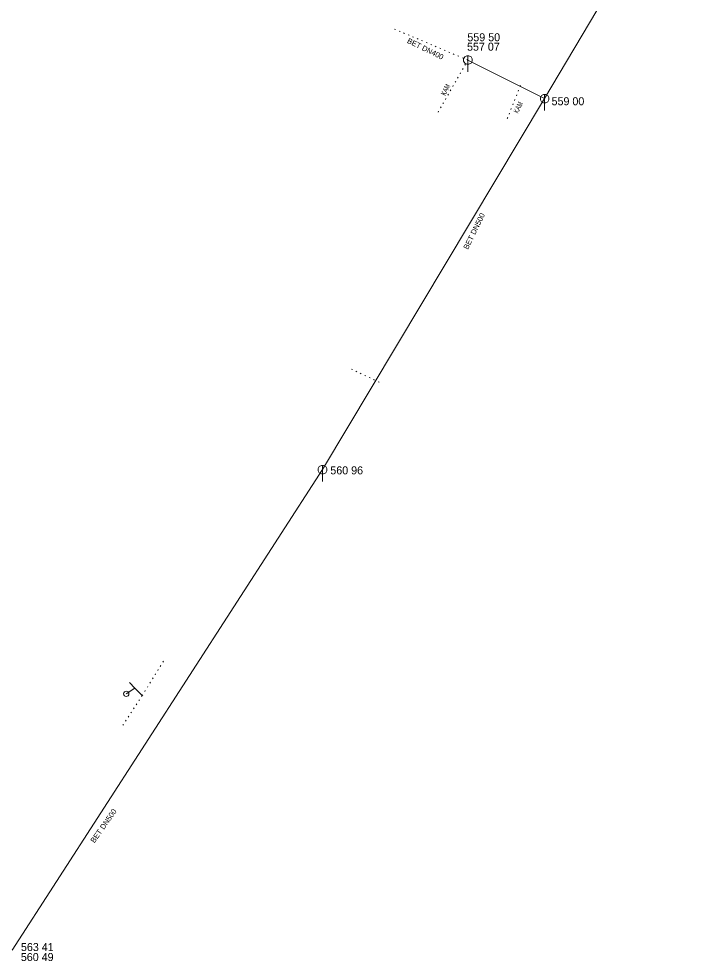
# Model space of a CAD drawing. Extents: x -710806 to -710046, y -1116920 to -1116046.
# Drawn here: x -710518.2 to -710454.5, y -1116662.7 to -1116574.5 of the extents above; entities that cross this region are included whole.
import ezdxf
from ezdxf.enums import TextEntityAlignment as Align

# ---------------------------------------------------------------- set-up
doc = ezdxf.new("R2010")
doc.units = 0
doc.header["$LTSCALE"] = 0.3
doc.linetypes.add('DOTTED', pattern=[1.5, 0.3, -1.2])
for name, color, linetype, lineweight in [('40', 7, 'Continuous', 13), ('41', 7, 'Continuous', 13), ('45', 7, 'DOTTED', 13)]:
    doc.layers.add(name, color=color, linetype=linetype, lineweight=lineweight)
doc.layers.add('43', color=7, linetype='Continuous')
doc.layers.add('44', color=7, linetype='Continuous')

msp = doc.modelspace()

# ---------------------------------------------------------------- linework, layer by layer
at = {"layer": '40'}
msp.add_line((-710468.921, -1116581.933), (-710454.536, -1116557.596), dxfattribs=at)
at = {"layer": '40', "linetype": 'DOTTED'}
for p, q in [((-710476.116, -1116578.317), (-710483.097, -1116575.374)), ((-710506.638, -1116637.858), (-710504.607, -1116634.576)), ((-710506.638, -1116637.858), (-710508.449, -1116640.634))]:
    msp.add_line(p, q, dxfattribs=at)
at = {"layer": '40'}
msp.add_lwpolyline([(-710518.824, -1116661.703), (-710489.738, -1116616.69), (-710468.921, -1116581.933), (-710476.116, -1116578.317)], dxfattribs=at)
at = {"layer": '41'}
for p, q in [((-710476.116, -1116577.917), (-710476.116, -1116579.417)), ((-710468.921, -1116581.533), (-710468.921, -1116583.033)), ((-710489.738, -1116616.29), (-710489.738, -1116617.79))]:
    msp.add_line(p, q, dxfattribs=at)
for points in [[(-710476.516, -1116578.417), (-710476.516, -1116578.217), (-710476.416, -1116578.017), (-710476.216, -1116577.917), (-710476.016, -1116577.917), (-710475.816, -1116578.017), (-710475.716, -1116578.217), (-710475.716, -1116578.417), (-710475.816, -1116578.617), (-710476.016, -1116578.717), (-710476.216, -1116578.717), (-710476.416, -1116578.617)], [(-710469.321, -1116582.033), (-710469.321, -1116581.833), (-710469.221, -1116581.633), (-710469.021, -1116581.533), (-710468.821, -1116581.533), (-710468.621, -1116581.633), (-710468.521, -1116581.833), (-710468.521, -1116582.033), (-710468.621, -1116582.233), (-710468.821, -1116582.333), (-710469.021, -1116582.333), (-710469.221, -1116582.233)], [(-710490.138, -1116616.79), (-710490.138, -1116616.59), (-710490.038, -1116616.39), (-710489.838, -1116616.29), (-710489.638, -1116616.29), (-710489.438, -1116616.39), (-710489.338, -1116616.59), (-710489.338, -1116616.79), (-710489.438, -1116616.99), (-710489.638, -1116617.09), (-710489.838, -1116617.09), (-710490.038, -1116616.99)]]:
    msp.add_lwpolyline(points, close=True, dxfattribs=at)
msp.add_circle((-710508.129, -1116637.691), 0.25, dxfattribs=at)
at = {"layer": '45'}
for p, q in [((-710476.116, -1116578.317), (-710478.969, -1116583.307)), ((-710471.198, -1116580.714), (-710472.455, -1116583.888)), ((-710484.445, -1116608.494), (-710487.293, -1116607.147))]:
    msp.add_line(p, q, dxfattribs=at)
at = {"layer": '45', "linetype": 'Continuous'}
msp.add_line((-710507.321, -1116637.155), (-710507.829, -1116636.63), dxfattribs=at)
msp.add_lwpolyline([(-710508.129, -1116637.691), (-710507.321, -1116637.155), (-710506.638, -1116637.858)], dxfattribs=at)

# ---------------------------------------------------------------- texts
at = {"layer": '43'}
for s, p in [('559 50 ', (-710474.4912, -1116576.557)), ('559 00 ', (-710466.5992, -1116582.552)), ('560 96 ', (-710487.3332, -1116617.13)), ('563 41 ', (-710516.3252, -1116661.788))]:
    msp.add_text(s, height=0.75, dxfattribs=at).set_placement(p, align=Align.CENTER)
for s, p in [('557 07', (-710476.195, -1116577.439)), ('560 49', (-710518.009, -1116662.725))]:
    msp.add_text(s, height=0.75, dxfattribs=at).set_placement(p)
at = {"layer": '44'}
for s, rotation, p in [('BET DN400', 333.9, (-710481.86, -1116576.68)), ('BET DN500', 63.9, (-710476.116, -1116596.109)), ('BET DN500', 54.9, (-710511.113, -1116651.708))]:
    msp.add_text(s, height=0.5, rotation=rotation, dxfattribs=at).set_placement(p)
at = {"layer": '44', "width": 0.6}
for p in [(-710478.236, -1116581.692), (-710471.423, -1116583.358)]:
    msp.add_text('KAM', height=0.5, rotation=63, dxfattribs=at).set_placement(p)

doc.saveas('drawing.dxf')
